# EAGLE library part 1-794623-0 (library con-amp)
MICRO MATE N LOK Dual Row, grid 1.5 mm Source: http://catalog.tycoelectronics.com .. ENG_CD_794623_F.pdf
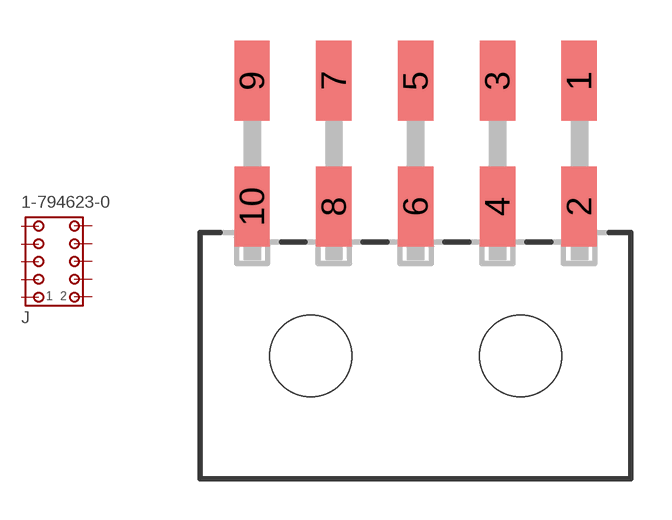
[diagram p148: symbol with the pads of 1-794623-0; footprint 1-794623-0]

Designator prefix J

## 1-794623-0 (MF: TYCO ELECTRONICS; MPN: 1-794623-0; OC_FARNELL: unknown; OC_NEWARK: 10H3682)  [1-794623-0]
1  1  pas
2  2  pas
3  3  pas
4  4  pas
5  5  pas
6  6  pas
7  7  pas
8  8  pas
9  9  pas
10  10  pas

## Footprint 1-794623-0 (pad centres in mm)
MICRO MATE N LOK Dual Row, grid 1.5 mm Source: http://catalog.tycoelectronics.com .. ENG_CD_794623_F.pdf
smd 1.3 x 2.92: 1 6,10.1; 2 6,5.48; 3 3,10.1; 4 3,5.48; 5 0,10.1; 6 0,5.48; 7 -3,10.1; 8 -3,5.48; 9 -6,10.1; 10 -6,5.48
hole 3 at -3.85,0
hole 3 at 3.85,0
